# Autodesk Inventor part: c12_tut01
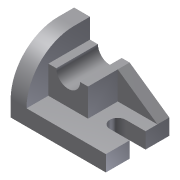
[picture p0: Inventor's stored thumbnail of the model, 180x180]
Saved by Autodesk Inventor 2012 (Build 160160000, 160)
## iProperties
Shininess: 77.0
Length Units: 11269
Angle Units: 11279
Time Units: 11290
Mass Units: 11283
Length Display Precision: 3
Angle Display Precision: 2
Created: 2001-11
Part Number: c12_tut01
Document SubType Name: Modeling
Designer: Renu Muthoo
Density: 1 g/cm^3
Material: Default
Density: 0.0
Volumn: 0.0
Area: 0.0
PropertySet Name: Model Information
Control State: 0
Master: False
Checked Out: False
Author: Renu Muthoo
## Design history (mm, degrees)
sketch "Sketch1"
  geometry: L1 (-48, 36)-(48, 36); L2 (48, -28)-(-48, -28); L3 (-48, -28)-(-48, 36); L4 (48, 12)-(28, 12); L5 (28, -4)-(48, -4); L6 (48, 36)-(48, 12); L7 (48, -4)-(48, -28); A1 r 8 centre (28, 4) between (28, 12) and (28, -4)
  constraints: 14 end point, 4 parallel, 3 perpendicular, 2 point on circle, 2 tangent, 1 centre point, 1 collinear, 1 horizontal
  dimensions: "d0" = 96 distance of L2.start L2.end; "d1" = 64 distance of L2.end L1.start; "d2" = 20 distance of L4.start L4.end; "d3" = 24 distance between parallel lines of L2 L5; "d4" = 16 distance between parallel lines of L4 L5
extrude "Extrusion1" new body sketch "Sketch1" distance "d5" = 16; taper "d6" = 0 deg
sketch "Sketch2"
  geometry: L1 (16, 64)-(64, 64); L2 (64, 64)-(64, 48); L3 (16, 0)-(16, 0); L4 (16, 0)-(16, 64); L5 (0, 64)-(16, 64) reference; L6 (16, 0)-(16, 64) reference; L7 (0, 0)-(16, 0) reference; L8 (0, 0)-(0, 64) reference; A1 r 48 centre (16, 48) between (16, 0) and (64, 48)
  constraints: 8 end point, 3 collinear, 3 perpendicular, 2 point on circle, 2 tangent, 1 centre point, 1 horizontal
  dimensions: "d7" = 64 distance between parallel lines of L2 L8; "d8" = 48 radius of A1
extrude "Extrusion2" join sketch "Sketch2" distance "d9" = 16; taper "d10" = 0 deg
sketch "Sketch3"
  geometry: L1 (16, -44)-(16, -16); L2 (16, -16)-(56, -16); L3 (56, -16)-(56, -44); L4 (56, -44)-(48, -44); L5 (24, -44)-(16, -44); L6 (16, -64)-(16, -16) reference; L7 (16, -16)-(96, -16) reference; A1 r 12 centre (36, -44) between (48, -44) and (24, -44)
  constraints: 10 end point, 3 collinear, 3 parallel, 2 equal length, 2 point on circle, 1 centre point, 1 perpendicular, 1 point on line, 1 vertical
  dimensions: "d11" = 28 distance of L2.end L3.end; "d12" = 8 distance of L3.end L4.end; "d13" = 24 distance of L5.start L4.end
extrude "Extrusion3" join sketch "Sketch3" distance "d14" = 42; taper "d15" = 0 deg
sketch "Sketch4"
  geometry: L1 (56, -16)-(96, -16) reference; L2 (56, -16)-(56, -44) reference; L3 (96, -16)-(56, -44)
  constraints: 2 end point
extrude "Extrusion4" join sketch "Sketch4" distance "d16" = 12; taper "d17" = 0 deg
body "Solid1"
